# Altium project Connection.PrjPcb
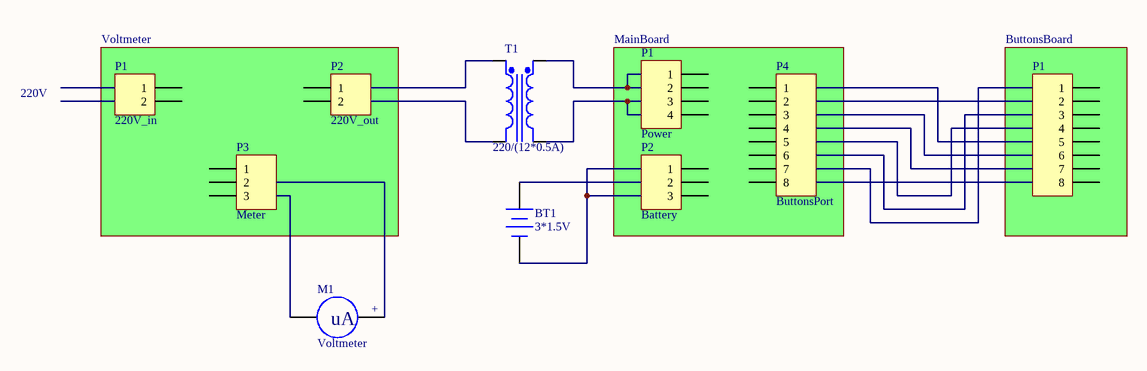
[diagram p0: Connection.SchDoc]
1 sheet, 10 parts. Net scope: global (net labels, ports and power ports of the same name join across sheets).

## Sheet Connection.SchDoc
size A4; PageSetup: Record=PageOptions|CenterHorizontal=True|CenterVertical=True|PrintScale=1.00|XCorrection=1.00|YCorrection=1.00|PrintKind=1|BorderSize=5000000|LeftOffset=0|BottomOffset=0|Orientation=2|PaperLength=1000|PaperWidth=1000|Scale=100|PaperSource=1|PrintQuality=300|MediaType=1|DitherType=10|PaperKind=A4|PrintScaleMode=1

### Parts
(Parts that share a designator on the sheet are numbered #1, #2 ... from top to bottom, then left to right.)
BT1  3*1.5V  [BAT-2]
M1  Voltmeter  [RAD-0.1]
P1#1  Power  [HDR1X4]
P1#2  220V_in  [HDR1X2]
P1#3  Header 8  [HDR1X8]  (value not drawn)
P2#1  220V_out  [HDR1X2]
P2#2  Battery  [HDR1X3]
P3  Meter  [HDR1X3]
P4  ButtonsPort  [HDR1X8]
T1  220/(12*0.5A)  [TRF_4]

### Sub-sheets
  = ButtonsBoard (file not in this document): no entries
? = Voltmeter (file not in this document): no entries
? = MainBoard (file not in this document): no entries

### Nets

Not connected (* = marked no-connect by the designer): BT1 1(+) 2(-); M1 1 2; P1#1 1 2 3 4; P1#2 1 2; P1#3 1 2 3 4 5 6 7 8; P2#1 1 2; P2#2 1 2 3; P3 1 2 3; P4 1 2 3 4 5 6 7 8; T1 1(Pri+) 2(Pri-) 3(Sec+) 4(Sec-)

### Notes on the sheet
- 220V
- (near M1) uA
- (near M1) +

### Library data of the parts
BT1 = Battery: Multicell Battery
M1 = Meter: Indicating Instrument; Note: Place a "letter" into the symbol to show the function of the meter or instrument
P1#1 = Header 4: Header, 4-Pin
P1#2 P2#1 = Header 2: Header, 2-Pin
P1#3 P4 = Header 8: Header, 8-Pin
P2#2 P3 = Header 3: Header, 3-Pin
T1 = Trans Ideal: Transformer (Ideal)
